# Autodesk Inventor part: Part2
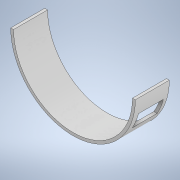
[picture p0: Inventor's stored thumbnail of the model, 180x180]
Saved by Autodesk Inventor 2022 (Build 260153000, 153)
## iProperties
Created: 2021-06
Part Number: Part2
Material: Generic
Document SubType Name: Modeling
Designer: USER
Density: 1 g/cm^3
Appearance: Default
Author: USER
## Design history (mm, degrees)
sketch "Sketch1"
  geometry: L1 (-55, 0)-(55, 0); A1 r 55 centre (0, 0) between (-55, 0) and (55, 0); A2 r 52.5 centre (0, 0) between (-52.5, 0) and (52.5, 0); 1 further point
  constraints: 4 point on circle, 2 centre point, 2 coincident, 2 end point, 2 point on line, 1 horizontal
extrude "Extrusion1" new body sketch "Sketch1" distance "d2" = 30; taper "d3" = 0 deg
workplane "Work Plane1"
sketch "Sketch2"
  geometry: L1 (-13.703, 25.439)-(-27.271, 25.439); L2 (-27.271, 25.439)-(-27.271, 3.46); L3 (-27.271, 3.46)-(-13.703, 3.46); L4 (-13.703, 3.46)-(-13.703, 25.439); 1 further point
  constraints: 8 end point, 2 parallel, 1 horizontal, 1 perpendicular
extrude "Extrusion2" cut sketch "Sketch2" distance "d5" = 30; taper "d6" = 0 deg
body "Solid1"
other parameters: "d4" = 55
